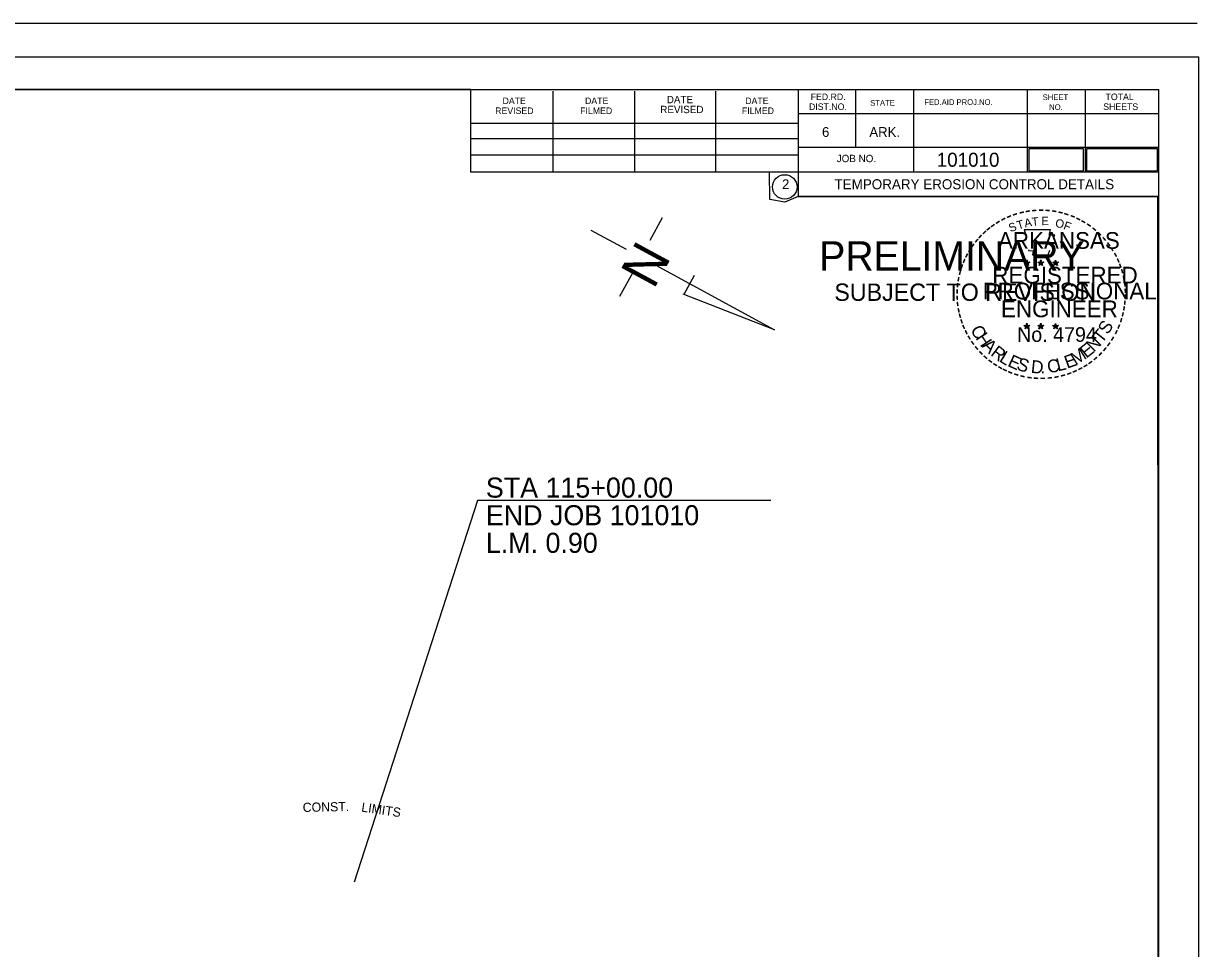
# Model space of a CAD drawing. Extents: x 9525 to 11605, y 9961 to 11067.
# Drawn here: x 10902 to 11605, y 10514 to 11067 of the extents above; entities that cross this region are included whole.
import ezdxf

# ---------------------------------------------------------------- set-up
doc = ezdxf.new("R2010")
doc.units = 0
for name, color, linetype in [('C-PSVP', 7, 'Continuous'), ('Clearing and Grubbing Ditch Checks', 7, 'Continuous'), ('Clearing and Grubbing Silt Fence', 7, 'Continuous'), ('GREEN_TXT', 7, 'Continuous'), ('SEAL-INFO', 7, 'Continuous'), ('SIGNATURE', 7, 'Continuous'), ('Stage 1 Construction', 7, 'Continuous'), ('Stage 1 Ditch Checks', 7, 'Continuous'), ('Stage 2 Flow Arrows', 7, 'Continuous'), ('Stage 2 Main Temp Seeding', 7, 'Continuous')]:
    doc.layers.add(name, color=color, linetype=linetype)

msp = doc.modelspace()

# ---------------------------------------------------------------- linework, layer by layer
for p, q in [((11284.1, 10950.44), (11276.74, 10936.88)), ((11241.41, 10943.19), (11262.43, 10931.77)), ((11266.43, 10917.91), (11258.56, 10903.42)), ((11279.76, 10922.36), (11351.25, 10883.52)), ((11303.19, 10916.05), (11297.02, 10904.69)), ((11351.25, 10883.52), (11296.64, 10904.9))]:
    msp.add_line(p, q)
at = {"layer": 'C-PSVP'}
for p, q in [((11500.31, 10924.04), (11502.05, 10923.49)), ((11500.31, 10924.04), (11501.57, 10923.82)), ((11500.31, 10924.04), (11501.49, 10923.43)), ((11500.97, 10922), (11502.05, 10923.49)), ((11500.97, 10922), (11501.6, 10923.22)), ((11500.97, 10922), (11502.04, 10923.09)), ((11502.05, 10925.31), (11501.85, 10924.05)), ((11503.12, 10922), (11502.04, 10923.07)), ((11502.05, 10923.49), (11502.05, 10925.31)), ((11502.05, 10925.31), (11502.3, 10924.06)), ((11503.79, 10924.04), (11502.05, 10923.49)), ((11503.12, 10922), (11502.05, 10923.49)), ((11503.79, 10924.04), (11502.36, 10923.8)), ((11503.12, 10922), (11502.43, 10923.46)), ((11503.79, 10924.04), (11502.77, 10923.53)), ((11508.66, 10924.04), (11510.4, 10923.49)), ((11508.66, 10924.04), (11509.92, 10923.82)), ((11508.66, 10924.04), (11509.84, 10923.43)), ((11509.32, 10922), (11510.4, 10923.49)), ((11509.32, 10922), (11509.95, 10923.22)), ((11509.32, 10922), (11510.39, 10923.09)), ((11510.4, 10925.31), (11510.2, 10924.05)), ((11511.47, 10922), (11510.39, 10923.07)), ((11510.4, 10923.49), (11510.4, 10925.31)), ((11510.4, 10925.31), (11510.65, 10924.06)), ((11512.14, 10924.04), (11510.4, 10923.49)), ((11511.47, 10922), (11510.4, 10923.49)), ((11512.14, 10924.04), (11510.71, 10923.8)), ((11511.47, 10922), (11510.78, 10923.46)), ((11512.14, 10924.04), (11511.12, 10923.53)), ((11517.48, 10923.98), (11519.22, 10923.43)), ((11517.48, 10923.98), (11518.74, 10923.76)), ((11517.48, 10923.98), (11518.66, 10923.37)), ((11518.14, 10921.94), (11519.22, 10923.43)), ((11518.14, 10921.94), (11518.77, 10923.16)), ((11518.14, 10921.94), (11519.21, 10923.03)), ((11519.22, 10925.25), (11519.02, 10923.99)), ((11519.22, 10923.43), (11519.22, 10925.25)), ((11519.22, 10925.25), (11519.47, 10924)), ((11520.96, 10923.98), (11519.22, 10923.43)), ((11520.29, 10921.94), (11519.22, 10923.43)), ((11520.96, 10923.98), (11519.53, 10923.74)), ((11520.29, 10921.94), (11519.6, 10923.4)), ((11520.96, 10923.98), (11519.94, 10923.47)), ((11520.29, 10921.94), (11519.21, 10923.01)), ((11500.29, 10886.18), (11502.03, 10885.62)), ((11500.29, 10886.18), (11501.55, 10885.95)), ((11500.29, 10886.18), (11501.47, 10885.57)), ((11500.95, 10884.14), (11502.03, 10885.62)), ((11500.95, 10884.14), (11501.58, 10885.36)), ((11500.95, 10884.14), (11502.02, 10885.22)), ((11502.03, 10887.45), (11501.83, 10886.19)), ((11503.1, 10884.14), (11502.02, 10885.21)), ((11502.03, 10885.62), (11502.03, 10887.45)), ((11502.03, 10887.45), (11502.28, 10886.2)), ((11503.77, 10886.18), (11502.03, 10885.62)), ((11503.1, 10884.14), (11502.03, 10885.62)), ((11503.77, 10886.18), (11502.34, 10885.93)), ((11503.1, 10884.14), (11502.41, 10885.59)), ((11503.77, 10886.18), (11502.75, 10885.67)), ((11508.63, 10886.18), (11510.38, 10885.62)), ((11508.63, 10886.18), (11509.9, 10885.95)), ((11508.63, 10886.18), (11509.82, 10885.57)), ((11509.3, 10884.14), (11510.38, 10885.62)), ((11509.3, 10884.14), (11509.93, 10885.36)), ((11509.3, 10884.14), (11510.37, 10885.22)), ((11510.38, 10887.45), (11510.17, 10886.19)), ((11511.44, 10884.14), (11510.37, 10885.21)), ((11510.38, 10885.62), (11510.38, 10887.45)), ((11510.38, 10887.45), (11510.62, 10886.2)), ((11512.11, 10886.18), (11510.38, 10885.62)), ((11511.44, 10884.14), (11510.38, 10885.62)), ((11512.11, 10886.18), (11510.68, 10885.93)), ((11511.44, 10884.14), (11510.76, 10885.59)), ((11512.11, 10886.18), (11511.09, 10885.67)), ((11517.47, 10886.13), (11519.21, 10885.57)), ((11517.47, 10886.13), (11518.73, 10885.9)), ((11517.47, 10886.13), (11518.65, 10885.52)), ((11518.13, 10884.09), (11519.21, 10885.57)), ((11518.13, 10884.09), (11518.76, 10885.31)), ((11518.13, 10884.09), (11519.2, 10885.17)), ((11519.21, 10887.4), (11519.01, 10886.14)), ((11520.28, 10884.09), (11519.2, 10885.16)), ((11519.21, 10885.57), (11519.21, 10887.4)), ((11519.21, 10887.4), (11519.46, 10886.15)), ((11520.95, 10886.13), (11519.21, 10885.57)), ((11520.28, 10884.09), (11519.21, 10885.57)), ((11520.95, 10886.13), (11519.52, 10885.88)), ((11520.28, 10884.09), (11519.59, 10885.54)), ((11520.95, 10886.13), (11519.93, 10885.62))]:
    msp.add_line(p, q, dxfattribs=at)
for points in [[(11500.51, 10943.43), (11501.86, 10939.3)], [(11518.07, 10938.82), (11518.78, 10940.24), (11515.35, 10940.12), (11516.09, 10943.43), (11500.51, 10943.43)], [(11502.97, 10931.32), (11502.97, 10930.88), (11505.79, 10930.79), (11505.52, 10928.42), (11514.87, 10928.42), (11515.87, 10931.1)], [(11502.05, 10925.31), (11503.12, 10922), (11500.31, 10924.04), (11503.79, 10924.04), (11500.97, 10922), (11502.05, 10925.31)], [(11510.4, 10925.31), (11511.47, 10922), (11508.66, 10924.04), (11512.14, 10924.04), (11509.32, 10922), (11510.4, 10925.31)], [(11519.22, 10925.25), (11520.29, 10921.94), (11517.48, 10923.98), (11520.96, 10923.98), (11518.14, 10921.94), (11519.22, 10925.25)], [(11502.03, 10887.45), (11503.1, 10884.14), (11500.29, 10886.18), (11503.77, 10886.18), (11500.95, 10884.14), (11502.03, 10887.45)], [(11510.38, 10887.45), (11511.44, 10884.14), (11508.63, 10886.18), (11512.11, 10886.18), (11509.3, 10884.14), (11510.38, 10887.45)], [(11519.21, 10887.4), (11520.28, 10884.09), (11517.47, 10886.13), (11520.95, 10886.13), (11518.13, 10884.09), (11519.21, 10887.4)]]:
    msp.add_lwpolyline(points, dxfattribs=at)
for centre, radius in [((11502.05, 10923.48), 0.861), ((11502.05, 10923.48), 0.723), ((11502.05, 10923.48), 0.579), ((11502.05, 10923.48), 0.495), ((11502.05, 10923.48), 0.374), ((11502.05, 10923.48), 0.248), ((11502.05, 10923.48), 0.148), ((11510.4, 10923.48), 0.861), ((11510.4, 10923.48), 0.723), ((11510.4, 10923.48), 0.579), ((11510.4, 10923.48), 0.495), ((11510.4, 10923.48), 0.374), ((11510.4, 10923.48), 0.248), ((11510.4, 10923.48), 0.148), ((11519.22, 10923.42), 0.861), ((11519.22, 10923.42), 0.723), ((11519.22, 10923.42), 0.579), ((11519.22, 10923.42), 0.495), ((11519.22, 10923.42), 0.374), ((11519.22, 10923.42), 0.248), ((11519.22, 10923.42), 0.148), ((11502.03, 10885.62), 0.861), ((11502.03, 10885.62), 0.723), ((11502.03, 10885.62), 0.579), ((11502.03, 10885.62), 0.495), ((11502.03, 10885.62), 0.374), ((11502.03, 10885.62), 0.248), ((11502.03, 10885.62), 0.148), ((11510.37, 10885.62), 0.861), ((11510.37, 10885.62), 0.723), ((11510.37, 10885.62), 0.579), ((11510.37, 10885.62), 0.495), ((11510.37, 10885.62), 0.374), ((11510.37, 10885.62), 0.248), ((11510.37, 10885.62), 0.148), ((11519.21, 10885.57), 0.861), ((11519.21, 10885.57), 0.723), ((11519.21, 10885.57), 0.579), ((11519.21, 10885.57), 0.495), ((11519.21, 10885.57), 0.374), ((11519.21, 10885.57), 0.248), ((11519.21, 10885.57), 0.148)]:
    msp.add_circle(centre, radius, dxfattribs=at)
at = {"layer": 'Clearing and Grubbing Ditch Checks'}
msp.add_lwpolyline([(11503.22, 10978.65), (11535.88, 10978.65), (11535.88, 10991.85), (11503.22, 10991.85)], close=True, dxfattribs=at)
at = {"layer": 'Clearing and Grubbing Silt Fence'}
msp.add_lwpolyline([(11537.72, 10978.65), (11580.08, 10978.65), (11580.08, 10991.85), (11537.72, 10991.85)], close=True, dxfattribs=at)
at = {"layer": 'GREEN_TXT'}
for p, q in [((11603.9, 11066.7), (9843.9, 11066.7)), ((10000, 11027.3), (11580.9, 11027.3)), ((11169.6, 10977.9), (11169.6, 11027.3)), ((11218.9, 10977.9), (11218.9, 11026.3)), ((11267.7, 10977.9), (11267.7, 11026.3)), ((11316.1, 10977.9), (11316.1, 11026.3)), ((11365.4, 11027.3), (11365.4, 10963.3)), ((11399.6, 11027.3), (11399.6, 10992.6)), ((11434.3, 11027.3), (11434.3, 10977.9)), ((11502.2, 11027.3), (11502.2, 10977.9)), ((11536.9, 11027.3), (11536.9, 10977.9)), ((11580.9, 10000), (11580.9, 11027.3)), ((11580.9, 11012.6), (11365.4, 11012.6)), ((11580.9, 11012.7), (11580.9, 11012.7)), ((11169.6, 11007.2), (11365.4, 11007.2)), ((11169.6, 10997.9), (11365.4, 10997.9)), ((11169.6, 10988.2), (11365.4, 10988.2)), ((11580.9, 10992.6), (11365.4, 10992.6)), ((11580.9, 10977.9), (11169.6, 10977.9)), ((11365.4, 10963.3), (11580.9, 10963.3))]:
    msp.add_line(p, q, dxfattribs=at)
msp.add_circle((11357.33, 10968.98), 7.33, dxfattribs=at)
at = {"layer": 'SEAL-INFO'}
msp.add_lwpolyline([(9937.96, 11046.77), (11604.66, 11046.77), (11604.66, 9980.09), (9937.96, 9980.09)], close=True, dxfattribs=at)
at = {"layer": 'Stage 1 Construction'}
msp.add_lwpolyline([(11348.9, 10781.47), (11173.67, 10781.47), (11099.99, 10553.32)], dxfattribs=at)
at = {"layer": 'Stage 1 Ditch Checks'}
msp.add_lwpolyline([(10000, 10000), (11580.9, 10000), (11580.3, 10963.3), (11365.4, 10963.3), (11357.31, 10959.87), (11348.49, 10961.4), (11348.26, 10977.9), (11169.6, 10977.9), (11169.6, 11027.3), (10000, 11027.3)], close=True, dxfattribs=at)
msp.add_lwpolyline([(10000, 10000), (11580.9, 10000), (11580.3, 10963.3), (11365.4, 10963.3), (11357.31, 10959.87), (11348.49, 10961.4), (11348.26, 10977.9), (11169.6, 10977.9), (11169.6, 11027.3), (10000, 11027.3)], close=True, dxfattribs=at)

# ---------------------------------------------------------------- texts
msp.add_text('N', height=23.27, rotation=241.48958).set_placement((11269.24, 10938.11))
at = {"layer": 'C-PSVP'}
for s, height, rotation, p in [('-', 8, 24.30721, (11491.08, 10947.72)), ('-', 8, 19.17608, (11494.25, 10949.07)), ('-', 8, 13.63015, (11498, 10950.27)), ('-', 8, 10.21935, (11501.39, 10951.08)), ('-', 8, 5.89682, (11505.04, 10951.63)), ('-', 8, 0.18623, (11508.9, 10951.99)), ('E', 5, 0.83234, (11510.76, 10946.11)), ('-', 8, 357.74304, (11512.51, 10951.93)), ('-', 8, 352.16172, (11516.23, 10951.65)), ('-', 8, 347.20489, (11519.83, 10951.08)), ('-', 8, 342.3362, (11523, 10950.3)), ('-', 8, 337.85509, (11526.68, 10949.19)), ('-', 8, 38.95066, (11479.66, 10940.42)), ('-', 8, 36.23174, (11482.04, 10942.31)), ('-', 8, 34.06357, (11484.93, 10944.29)), ('-', 8, 28.79182, (11487.92, 10946.14)), ('S', 5, 21.59401, (11492.29, 10941.82)), ('T', 5, 16.4036, (11496.86, 10943.48)), ('A', 5, 11.21318, (11500.99, 10944.73)), ('T', 5, 6.02276, (11505.23, 10945.56)), ('O', 5, 350.4515, (11518.78, 10945.06)), ('F', 5, 340.07066, (11523.55, 10943.92)), ('-', 8, 334.12109, (11529.83, 10947.83)), ('-', 8, 329.64089, (11532.73, 10946.42)), ('-', 8, 325.86266, (11535.94, 10944.61)), ('-', 8, 320.52971, (11538.99, 10942.48)), ('-', 8, 50.61417, (11473.24, 10933.52)), ('-', 8, 48.42305, (11475.26, 10935.95)), ('-', 8, 42.96224, (11477.5, 10938.34)), ('-', 8, 315.57859, (11541.99, 10940.04)), ('-', 8, 309.87973, (11544.83, 10937.29)), ('-', 8, 58.07063, (11469.55, 10928.05)), ('-', 8, 54.23247, (11471.18, 10930.68)), ('-', 8, 306.65218, (11547.46, 10934.28)), ('-', 7, 303.67529, (11549.89, 10931.44)), ('-', 8, 67.77427, (11466.69, 10921.92)), ('-', 8, 62.87135, (11467.99, 10924.98)), ('-', 8, 299.66835, (11551.48, 10928.41)), ('-', 8, 294.66279, (11553.1, 10925.35)), ('-', 8, 290.57283, (11554.39, 10922.46)), ('-', 8, 75.46096, (11464.61, 10915.2)), ('-', 8, 72.39447, (11465.6, 10918.77)), ('-', 8, 285.12326, (11555.56, 10919.56)), ('-', 8, 280.54934, (11556.56, 10915.85)), ('-', 8, 85.18634, (11463.57, 10908.18)), ('-', 8, 81.20126, (11463.95, 10911.64)), ('-', 8, 276.59616, (11557.37, 10912.01)), ('-', 8, 94.19588, (11463.62, 10901.05)), ('-', 8, 89.06224, (11463.45, 10904.68)), ('-', 8, 274.33011, (11557.67, 10908.4)), ('-', 8, 269.94067, (11557.84, 10905.24)), ('-', 8, 98.94793, (11463.98, 10897.72)), ('-', 8, 101.71495, (11464.66, 10894.05)), ('-', 8, 260.99529, (11557.39, 10898.64)), ('-', 8, 263.5172, (11557.74, 10901.91)), ('-', 8, 105.45785, (11465.47, 10891.08)), ('-', 8, 109.08742, (11466.54, 10887.92)), ('S', 7.7, 57.878, (11550.49, 10880.28)), ('-', 8, 255.7626, (11555.88, 10891.81)), ('-', 8, 255.7626, (11556.84, 10895.25)), ('-', 8, 114.06432, (11467.81, 10884.94)), ('-', 8, 115.72885, (11469.34, 10881.85)), ('C', 7.7, 296.9133, (11468.18, 10883.9)), ('H', 7.7, 303.27986, (11471.13, 10878.7)), ('T', 7.7, 51.51144, (11546.85, 10875.07)), ('-', 8, 244.61971, (11553.51, 10885.14)), ('-', 8, 247.88866, (11554.82, 10888.29)), ('-', 8, 120.44712, (11471.12, 10878.92)), ('-', 8, 125.89344, (11473.14, 10876.12)), ('-', 8, 130.71812, (11475.45, 10873.36)), ('A', 7.7, 316.01299, (11474.77, 10873.57)), ('R', 7.7, 322.37955, (11479.9, 10868.66)), ('E', 7.7, 38.77831, (11537.6, 10866.21)), ('N', 7.7, 45.14487, (11542.05, 10869.86)), ('-', 8, 233.84524, (11549.53, 10878.12)), ('-', 8, 239.07125, (11551.54, 10881.38)), ('-', 8, 134.22381, (11478.03, 10870.63)), ('-', 8, 138.93382, (11480.66, 10868.31)), ('L', 7.7, 328.74612, (11485.03, 10864.91)), ('E', 7.7, 335.11268, (11490.06, 10862.12)), ('E', 7.7, 19.67862, (11526.09, 10860.26)), ('M', 7.7, 32.41175, (11531.2, 10862.15)), ('-', 8, 221.08509, (11542.37, 10869.92)), ('-', 8, 225.76533, (11544.98, 10872.47)), ('-', 8, 231.25377, (11547.38, 10875.29)), ('-', 8, 144.64634, (11483.44, 10866.28)), ('-', 8, 148.08978, (11486.24, 10864.43)), ('-', 8, 151.57039, (11489.14, 10862.8)), ('-', 8, 154.60019, (11491.75, 10861.57)), ('S', 7.7, 341.47924, (11495.39, 10859.96)), ('D', 7.7, 354.21237, (11504.22, 10857.9)), ('C', 7.7, 6.94549, (11514.65, 10857.71)), ('L', 7.7, 13.31206, (11520.57, 10858.66)), ('-', 8, 207.35684, (11534.17, 10863.9)), ('-', 8, 212.24909, (11536.96, 10865.63)), ('-', 8, 215.73633, (11539.63, 10867.56)), ('-', 8, 158.56121, (11494.87, 10860.3)), ('-', 8, 162.79826, (11498.3, 10859.23)), ('-', 8, 167.55551, (11501.88, 10858.41)), ('-', 8, 173.11546, (11505.74, 10857.86)), ('-', 8, 176.51827, (11509.48, 10857.6)), ('-', 8, 181.59176, (11513.2, 10857.69)), ('.', 7.7, 0.57893, (11510.09, 10857.52)), ('-', 8, 185.81666, (11517.24, 10858.07)), ('-', 8, 191.28576, (11520.92, 10858.73)), ('-', 8, 195.47429, (11524.57, 10859.73)), ('-', 8, 200.71842, (11527.95, 10860.94)), ('-', 8, 204.25161, (11531.05, 10862.3))]:
    msp.add_text(s, height=height, rotation=rotation, dxfattribs=at).set_placement(p)
for s, height, p in [('ARKANSAS', 10, (11484.78, 10931.99)), ('REGISTERED', 10, (11481.39, 10911.25)), ('PROFESSIONAL', 10, (11475.65, 10901.73)), ('ENGINEER', 10, (11486.58, 10891.1)), ('No. 4794', 8.785, (11496.21, 10876.35))]:
    msp.add_text(s, height=height, dxfattribs=at).set_placement(p)
at = {"layer": 'GREEN_TXT'}
for s, height, p in [('DATE', 3.91, (11188.6, 11018.5)), ('DATE', 3.91, (11237.9, 11018.5)), ('DATE', 4.396, (11286.8, 11019)), ('DATE', 3.91, (11333.7, 11018.5)), ('FED.RD.', 3.91, (11372.8, 11020.9)), ('FED.AID PROJ.NO.', 3.42, (11440.7, 11018)), ('SHEET', 3.42, (11511.5, 11020.9)), ('TOTAL', 3.91, (11549.1, 11020.9)), ('REVISED', 3.91, (11184.2, 11012.59)), ('FILMED', 3.91, (11235, 11012.59)), ('REVISED', 4.396, (11282.9, 11013.09)), ('FILMED', 3.91, (11331.7, 11012.59)), ('DIST.NO.', 3.91, (11371.8, 11015)), ('STATE', 3.42, (11408.4, 11017.5)), ('NO.', 3.42, (11515.4, 11015)), ('SHEETS', 3.91, (11547.7, 11015)), ('6', 5.86, (11379.6, 10998.9)), ('ARK.', 5.861, (11407.9, 10998.9)), ('JOB NO.', 4.396, (11388.4, 10983.8)), ('2', 5.86, (11355.7, 10967.69))]:
    msp.add_text(s, height=height, dxfattribs=at).set_placement(p)
at = {"layer": 'SIGNATURE'}
for s, height, p in [('PRELIMINARY', 17.5, (11377.93, 10919.01)), ('SUBJECT TO REVISION', 10.3756, (11386.98, 10900.86))]:
    msp.add_text(s, height=height, dxfattribs=at).set_placement(p)
at = {"layer": 'Stage 1 Construction'}
for s, p in [('STA 115+00.00', (11178.63, 10783.21)), ('END JOB 101010', (11178.63, 10766.71)), ('L.M. 0.90', (11178.63, 10750.21))]:
    msp.add_text(s, height=12, dxfattribs=at).set_placement(p)
at = {"layer": 'Stage 2 Flow Arrows'}
for s, rotation, p in [('CONST. ', 1.15316, (11069.2, 10595.26)), ('LIMITS', 351.74539, (11103.96, 10595.55))]:
    msp.add_text(s, height=5.5, rotation=rotation, dxfattribs=at).set_placement(p)
at = {"layer": 'Stage 2 Main Temp Seeding'}
for s, height, p in [('101010', 8.4, (11448.18, 10981.05)), ('TEMPORARY EROSION CONTROL DETAILS', 6, (11387.05, 10967.6))]:
    msp.add_text(s, height=height, dxfattribs=at).set_placement(p)

doc.saveas('drawing.dxf')
